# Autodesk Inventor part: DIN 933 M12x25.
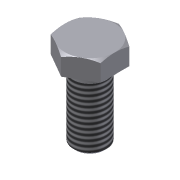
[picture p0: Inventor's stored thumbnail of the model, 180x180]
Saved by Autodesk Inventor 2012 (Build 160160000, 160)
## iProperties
Created: 2001-01
Part Number: DIN 933 M12x25.
Material: Steel, Mild
Document SubType Name: Modeling
Description: Sechskantschraube DIN 933 - M12x25.
Standard: DIN 933
Density: 7.86 g/cm^3
Company: CAD-Verlag
+MSCProtocol1+ProtocolID: P00040924061650206
+MSCProtocol2+Protocol: P00040924061650206<@PID>[Version]<@EL>Version=2.2<@EL>[Data]<@EL>mass=0.03870396{kg<@EL>b=21.5{mm<@EL>c=0.6{mm<@EL>dw=17{mm<@EL>r=0.6{mm<@EL>s=18{mm<@EL>d=12{mm
Control State: 0
Master: False
Checked Out: False
Shininess: 20.0
Length Units: 11269
Angle Units: 11279
Time Units: 11290
Mass Units: 11283
Length Display Precision: 3
Angle Display Precision: 2
BOM1: Sechskantschraube
BOM2: M12x25
BOM3: DIN 933
Density: 7.859999999999999
Volumn: 5.59798751986722
Area: 24.439342304675858
PropertySet Name: Model Information
Author: Jürgen Kronas
Revision Number: 1
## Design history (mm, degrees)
node "WorkPlane1"
node "Sketch1"
node "WorkPoint1"
extrude "ExtrusionBlind1" new body distance "d2" = 25 (= prf_l); taper "d3" = 0 deg
  node "Sketch2" dims "d1" = 12 (= prf_d)
chamfer "Chamfer1" distance "d4" = 0.875 (= msp_z); stored, may be unused: second distance "d5" = 0.875 (= msp_z), angle "d31" = 45 deg
node "WorkAxis1"
sketch "Sketch3" dims "d8" = 17 (= prf_dw)
  geometry: C1 r 6 at (0, 0) reference
  constraints: 1 other
extrude "ExtrusionBlind2" join sketch "Sketch3" distance "d9" = 0.6 (= prf_c); taper "d10" = 0 deg
sketch "Sketch4" dims "d13" = 18 (= prf_s)
  geometry: L1 (-9, 5.196)-(-9, -5.196); L2 (0, 10.392)-(-9, 5.196); L3 (9, 5.196)-(0, 10.392); L4 (9, -5.196)-(9, 5.196); L5 (0, -10.392)-(9, -5.196); L6 (-9, -5.196)-(0, -10.392); C1 r 8.5 at (0, 0) reference; C2 r 6 at (0, 0) reference; C3 r 5.125 at (0, 0) reference
  constraints: 12 end point, 4 vertical, 2 parallel, 7 other
extrude "ExtrusionBlind3" join sketch "Sketch4" distance "d14" = 6.9 (= -prf_c + prf_k); taper "d15" = 0 deg
sketch "Sketch5"
  geometry: L1 (-10.392, 6.696)-(-9, 7.5); L2 (0, -50.981)-(0, 0.981); L3 (0, -62.677)-(0, 19.196) reference; L4 (-9, 7.5)-(-10.392, 7.5); L5 (-10.392, 7.5)-(-10.392, 6.696); L6 (-10.392, 0.6)-(-10.392, 7.5) reference
  constraints: 8 end point, 2 perpendicular
  dimensions: "d20" = 0 distance between parallel lines of L6 L5; "d21" = 0 distance from line of L6.end L4; "d22" = 9 distance from line of L3 L1.end (= 0.5 x prf_s); "d23" = 60 deg angle of L6 L1
revolve "RevolutionFull1" sketch "Sketch5" stored, may be unused: angle "d18" = 360 deg
fillet "Fillet1" dims "d19" = 0.6 (= prf_r)
feature "Ms_Thread" dims "d25" = 0, "prf_b" = 21.5
node "MSC_A1"
node "MSC_PF1"
node "MSC_PT1"
node "Volumenkörper1"
node "Volumenkörpern"
node "Oberflächenkörpern"
other parameters: "prf_p" = 1.75 [user parameter; used in 1 equation term], "prf_l" = 25 [user parameter; used in 1 equation term], "prf_k" = 7.5 [user parameter; used in 1 equation term], "prf_d" = 12 [user parameter; used in 1 equation term], "prf_s" = 18 [user parameter; used in 2 equation terms], "prf_r" = 0.6 [user parameter; used in 1 equation term], "prf_dw" = 17 [user parameter; used in 1 equation term], "prf_c" = 0.6 [user parameter; used in 2 equation terms], "msp_z" = 0.875 (= 0.5 x prf_p) [user parameter; used in 2 equation terms], "d6" = 0, "d7" = 15 (derived), "d11" = 0, "d12" = 17 (derived), "d16" = 30 deg (derived), "d28" = 0, "d29" = 0, "d30" = 0
